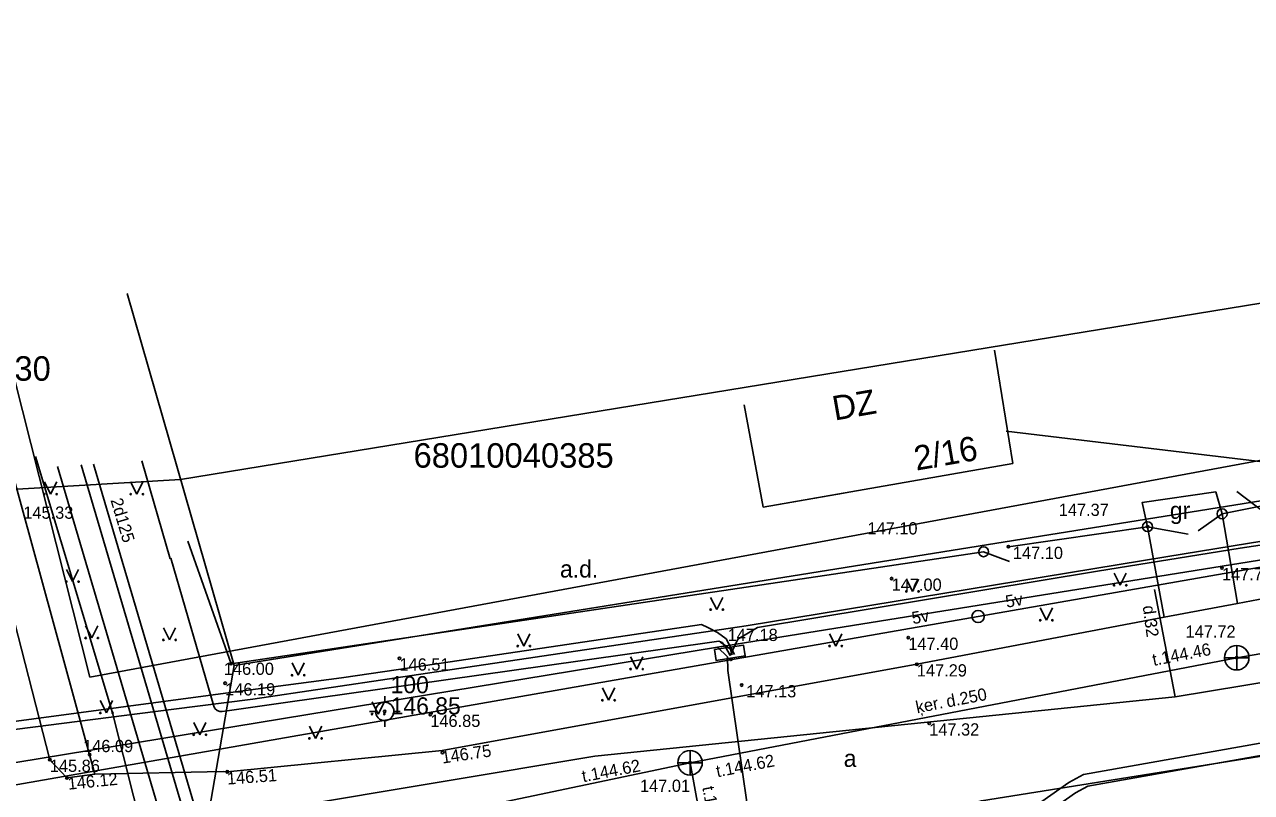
# Model space of a CAD drawing. Extents: x 728492 to 729038, y 272968 to 273171.
# Drawn here: x 728538.7 to 728588.9, y 273054.5 to 273085.8 of the extents above; entities that cross this region are included whole.
import ezdxf

# ---------------------------------------------------------------- set-up
doc = ezdxf.new("R2010")
doc.units = 0
for name, color, linetype in [('APGR_SARK_####_####_#', 7, 'Continuous'), ('BUVE_EKAS_####_####_#', 7, 'Continuous'), ('BUVE_EKAS_ADRS_TKST_#', 7, 'Continuous'), ('BUVE_EKAS_RAKS_TKST_#', 7, 'Continuous'), ('CELI_CAPM_####_####_#', 7, 'Continuous'), ('CELI_CMAL_####_####_#', 7, 'Continuous'), ('CELI_CSEG_####_TKST_#', 7, 'Continuous'), ('CELI_SEGL_####_####_#', 7, 'Continuous'), ('ELEK_ELEM_####_####_#', 7, 'Continuous'), ('ELEK_VADP_VSPR_####_#', 7, 'Continuous'), ('ELEK_VADP_ZSPR_####_#', 7, 'Continuous'), ('ELEK_VADV_ZSPR_####_#', 7, 'Continuous'), ('ELEK_VADV_ZSPR_TKST_#', 7, 'Continuous'), ('GEOD_ELEM_####_####_#', 7, 'Continuous'), ('GEOD_ELEM_####_TKST_#', 7, 'Continuous'), ('Level 7', 7, 'Continuous'), ('NORB_ELEM_####_####_#', 7, 'Continuous'), ('NORB_ZOGS_BARJ_####_#', 7, 'Continuous'), ('NORB_ZOGS_ZSTP_####_#', 7, 'Continuous'), ('RAMI_UZMR_####_####_#', 7, 'Continuous'), ('RELJ_AATZ_####_TKST_#', 7, 'Continuous'), ('RELJ_ELEM_####_####_#', 7, 'Continuous'), ('ROBZ_KADS_####_TKST_#', 7, 'Continuous'), ('ROBZ_UZMR_####_####_#', 7, 'Continuous'), ('SAKK_KKAN_####_####_#', 7, 'Continuous'), ('SAKT_VADP_KABE_####_#', 7, 'Continuous'), ('SAKT_VADV_KLIN_####_#', 7, 'Continuous'), ('SILT_VADP_UDEN_####_#', 7, 'Continuous'), ('SILT_VADP_UDEN_TKST_#', 7, 'Continuous'), ('SKAN_ELEM_####_####_#', 7, 'Continuous'), ('SKAN_VADP_PAST_####_#', 7, 'Continuous'), ('SKAN_VADP_PAST_TKST_#', 7, 'Continuous'), ('TERT_ELEM_####_####_#', 7, 'Continuous'), ('TERT_IZMT_####_TKST_#', 7, 'Continuous'), ('UDTK_VADP_UDEN_####_#', 7, 'Continuous'), ('UDTK_VADP_UDEN_TKST_#', 7, 'Continuous')]:
    doc.layers.add(name, color=color, linetype=linetype)

msp = doc.modelspace()

# ---------------------------------------------------------------- linework, layer by layer
at = {"layer": 'APGR_SARK_####_####_#'}
for points in [[(728659.143, 273080.982), (728541.407, 273059.185)], [(728541.407, 273059.185), (728536.919, 273076.93)]]:
    msp.add_lwpolyline(points, dxfattribs=at)
at = {"layer": 'BUVE_EKAS_####_####_#'}
for p, q in [((728578.38, 273072.545), (728579.123, 273067.904)), ((728568.928, 273066.121), (728568.149, 273070.31)), ((728579.123, 273067.904), (728568.928, 273066.121)), ((728572.204, 273066.694), (728568.928, 273066.121))]:
    msp.add_line(p, q, dxfattribs=at)
at = {"layer": 'CELI_CAPM_####_####_#'}
msp.add_line((728537.212, 273065.791), (728539.777, 273055.81), dxfattribs=at)
msp.add_lwpolyline([(728591.431, 273056.294), (728577.849, 273054.135), (728577.526, 273054.029), (728577.203, 273053.778), (728577.017, 273053.345), (728577.072, 273052.432)], dxfattribs=at)
at = {"layer": 'CELI_CMAL_####_####_#'}
for p, q in [((728541.62, 273055.225), (728538.209, 273067.671)), ((728588.309, 273062.194), (728590.22, 273062.556)), ((728575.205, 273059.709), (728585.316, 273061.626)), ((728555.804, 273056.19), (728575.205, 273059.709)), ((728547.029, 273055.314), (728555.804, 273056.19)), ((728541.62, 273055.225), (728546.857, 273055.329)), ((728546.857, 273055.329), (728547.029, 273055.314))]:
    msp.add_line(p, q, dxfattribs=at)
for points in [[(728584.631, 273065.328), (728584.407, 273066.315), (728587.419, 273066.752), (728587.68, 273065.855)], [(728587.68, 273065.855), (728588.309, 273062.194)], [(728584.631, 273065.328), (728585.316, 273061.626)], [(728541.62, 273055.225), (728541.62, 273055.225), (728540.474, 273055.066), (728539.777, 273055.81)]]:
    msp.add_lwpolyline(points, dxfattribs=at)
at = {"layer": 'CELI_SEGL_####_####_#'}
msp.add_line((728585.316, 273061.626), (728588.309, 273062.194), dxfattribs=at)
at = {"layer": 'ELEK_ELEM_####_####_#'}
msp.add_lwpolyline([(728566.936, 273060.306), (728568.121, 273060.494), (728568.191, 273060.05), (728567.006, 273059.861)], close=True, dxfattribs=at)
msp.add_circle((728577.706, 273061.659), 0.25, dxfattribs=at)
at = {"layer": 'ELEK_VADP_VSPR_####_#'}
for points in [[(728609.286, 273080.058), (728607.971, 273079.223), (728608.297, 273067.03), (728567.061, 273060.412)], [(728528.24, 273065.605), (728528.561, 273065.605), (728531.497, 273054.565), (728567.061, 273060.412)]]:
    msp.add_lwpolyline(points, dxfattribs=at)
at = {"layer": 'ELEK_VADP_ZSPR_####_#'}
for points in [[(728537.081, 273033.933), (728536.029, 273037.608), (728532.423, 273051.927), (728532.247, 273053.87), (728532.195, 273055.313), (728532.733, 273055.949), (728533.306, 273056.402), (728544.74, 273057.861), (728548.075, 273058.286), (728556.859, 273059.593), (728568.226, 273061.284), (728585.454, 273064.109), (728594.552, 273065.598), (728599.536, 273066.281), (728606.829, 273067.282), (728608.394, 273067.733), (728608.806, 273068.923), (728608.813, 273069.373), (728608.935, 273077.264)], [(728609.132, 273076.972), (728609.028, 273069.268), (728608.736, 273067.883), (728608.238, 273067.455), (728607.796, 273067.368), (728594.151, 273065.314), (728588.415, 273064.454), (728582.59, 273063.515), (728568.697, 273061.216), (728567.895, 273060.73), (728567.578, 273060.071)], [(728543.537, 273068.016), (728544.691, 273064.02)], [(728544.718, 273064.048), (728546.483, 273057.995), (728546.526, 273057.907), (728546.614, 273057.824), (728546.728, 273057.782), (728546.813, 273057.782), (728547.021, 273057.811), (728549.405, 273058.149), (728559.999, 273059.648), (728566.831, 273060.615), (728567.112, 273060.646), (728567.249, 273060.596), (728567.381, 273060.426), (728567.578, 273060.071)], [(728567.753, 273060.114), (728567.41, 273060.752), (728567.065, 273061.013), (728566.663, 273061.214), (728566.411, 273061.34), (728554.029, 273059.497), (728551.697, 273059.159), (728548.184, 273058.69), (728544.318, 273058.174), (728533.922, 273056.787), (728532.347, 273056.437), (728531.53, 273056.671), (728530.78, 273059.779)], [(728568.854, 273049.927), (728567.486, 273059.454), (728567.463, 273060.008)]]:
    msp.add_lwpolyline(points, dxfattribs=at)
at = {"layer": 'ELEK_VADV_ZSPR_####_#'}
for p, q in [((728577.706, 273061.659), (728617.923, 273068.708)), ((728530.877, 273053.467), (728577.706, 273061.659))]:
    msp.add_line(p, q, dxfattribs=at)
at = {"layer": 'GEOD_ELEM_####_####_#'}
for p, q in [((728553.461, 273058.158), (728553.461, 273058.408)), ((728552.836, 273057.783), (728553.086, 273057.783)), ((728553.461, 273057.158), (728553.461, 273057.408)), ((728553.836, 273057.783), (728554.086, 273057.783))]:
    msp.add_line(p, q, dxfattribs=at)
for radius in [0.375, 0.05]:
    msp.add_circle((728553.461, 273057.783), radius, dxfattribs=at)
at = {"layer": 'Level 7'}
msp.add_line((728567.061, 273060.412), (728567.463, 273060.008), dxfattribs=at)
msp.add_lwpolyline([(728567.182, 273060.614), (728567.584, 273060.331), (728567.665, 273060.089)], dxfattribs=at)
at = {"layer": 'NORB_ELEM_####_####_#'}
for centre in [(728587.68, 273065.855), (728584.631, 273065.328), (728577.931, 273064.305)]:
    msp.add_circle(centre, 0.202, dxfattribs=at)
at = {"layer": 'NORB_ZOGS_BARJ_####_#'}
for points in [[(728586.696, 273065.158), (728587.68, 273065.855)], [(728584.631, 273065.328), (728586.285, 273065.026)], [(728577.931, 273064.305), (728578.991, 273063.904)]]:
    msp.add_lwpolyline(points, dxfattribs=at)
at = {"layer": 'NORB_ZOGS_ZSTP_####_#'}
for points in [[(728587.68, 273065.855), (728594.005, 273067.114)], [(728578.944, 273064.509), (728584.631, 273065.328)], [(728545.412, 273064.735), (728547.181, 273059.731), (728577.931, 273064.305)]]:
    msp.add_lwpolyline(points, dxfattribs=at)
at = {"layer": 'RAMI_UZMR_####_####_#'}
for points in [[(728726.814, 273102.175), (728686.914, 273096.216), (728659.323, 273094.615), (728619.629, 273079.414), (728545.121, 273067.256)], [(728545.121, 273067.256), (728525.538, 273066.106), (728511.145, 273059.016), (728527.731, 273033.328), (728550.271, 273033.197), (728572.013, 273034.886), (728580.562, 273045.27), (728653.673, 273058.931), (728671.713, 273053.291), (728688.721, 273058.407), (728702.149, 273066.922)]]:
    msp.add_lwpolyline(points, dxfattribs=at)
at = {"layer": 'RELJ_ELEM_####_####_#'}
for centre in [(728584.631, 273065.328), (728578.944, 273064.509), (728587.672, 273063.64), (728574.174, 273063.211), (728574.855, 273060.797), (728554.064, 273059.951), (728567.609, 273059.906), (728588.276, 273059.976), (728547.181, 273059.731), (728575.205, 273059.709), (728546.942, 273058.935), (728568.047, 273058.857), (728553.461, 273057.783), (728555.323, 273057.647), (728575.71, 273057.297), (728539.777, 273055.81), (728541.407, 273056.021), (728555.821, 273056.102), (728547.029, 273055.314), (728565.936, 273055.685), (728540.474, 273055.066)]:
    msp.add_circle(centre, 0.05, dxfattribs=at)
at = {"layer": 'ROBZ_UZMR_####_####_#'}
for p, q in [((728547.311, 273059.662), (728542.932, 273074.849)), ((728597.584, 273067.721), (728547.311, 273059.662)), ((728547.311, 273059.662), (728544.976, 273046.06))]:
    msp.add_line(p, q, dxfattribs=at)
at = {"layer": 'SAKK_KKAN_####_####_#'}
msp.add_lwpolyline([(728540.095, 273067.793), (728546.092, 273047.448), (728546.377, 273046.751), (728547.961, 273042.009), (728549.129, 273037.471), (728550.271, 273033.197)], dxfattribs=at)
at = {"layer": 'SAKT_VADP_KABE_####_#'}
msp.add_lwpolyline([(728549.129, 273037.471), (728545.783, 273044.05), (728542.34, 273057.723), (728539.193, 273068.196)], dxfattribs=at)
at = {"layer": 'SAKT_VADV_KLIN_####_#'}
msp.add_line((728578.857, 273069.237), (728635.134, 273062.502), dxfattribs=at)
at = {"layer": 'SILT_VADP_UDEN_####_#'}
for p, q in [((728547.012, 273047.706), (728541.056, 273067.855)), ((728547.492, 273047.847), (728541.567, 273067.888))]:
    msp.add_line(p, q, dxfattribs=at)
for points in [[(728554.662, 273032.952), (728554.113, 273035.473), (728554.267, 273035.774), (728581.419, 273054.878), (728582.018, 273055.208), (728610.89, 273060.328), (728630.183, 273063.782), (728638.039, 273065.289), (728652.893, 273068.386), (728653.925, 273076.859), (728654.802, 273077.089)], [(728555.193, 273032.922), (728554.64, 273035.405), (728554.656, 273035.436), (728581.684, 273054.453), (728582.187, 273054.73), (728610.978, 273059.835), (728630.274, 273063.29), (728638.144, 273064.8), (728653.493, 273067.873), (728654.384, 273076.462), (728654.897, 273076.597)]]:
    msp.add_lwpolyline(points, dxfattribs=at)
at = {"layer": 'SKAN_ELEM_####_####_#'}
for p, q in [((728588.276, 273059.476), (728588.276, 273060.476)), ((728587.776, 273059.976), (728588.776, 273059.976)), ((728565.936, 273055.185), (728565.936, 273056.185)), ((728565.436, 273055.685), (728566.436, 273055.685))]:
    msp.add_line(p, q, dxfattribs=at)
for centre in [(728588.276, 273059.976), (728565.936, 273055.685)]:
    msp.add_circle(centre, 0.5, dxfattribs=at)
at = {"layer": 'SKAN_VADP_PAST_####_#'}
for points in [[(728565.936, 273055.685), (728588.276, 273059.976), (728595.572, 273061.244), (728588.275, 273066.761)], [(728536.573, 273049.518), (728565.936, 273055.685), (728568.908, 273039.465), (728569.266, 273036.186)]]:
    msp.add_lwpolyline(points, dxfattribs=at)
at = {"layer": 'TERT_ELEM_####_####_#'}
for p, q in [((728539.56, 273067.157), (728539.81, 273066.657)), ((728539.81, 273066.657), (728540.06, 273067.157)), ((728543.08, 273067.157), (728543.33, 273066.657)), ((728543.33, 273066.657), (728543.58, 273067.157)), ((728540.452, 273063.584), (728540.702, 273063.084)), ((728540.702, 273063.084), (728540.952, 273063.584)), ((728583.264, 273063.436), (728583.514, 273062.936)), ((728583.514, 273062.936), (728583.764, 273063.436)), ((728574.776, 273063.184), (728575.026, 273062.684)), ((728575.026, 273062.684), (728575.276, 273063.184)), ((728566.779, 273062.442), (728567.029, 273061.942)), ((728567.029, 273061.942), (728567.279, 273062.442)), ((728580.246, 273062.008), (728580.496, 273061.508)), ((728580.496, 273061.508), (728580.746, 273062.008)), ((728541.241, 273061.282), (728541.491, 273060.782)), ((728541.491, 273060.782), (728541.741, 273061.282)), ((728544.418, 273061.202), (728544.668, 273060.702)), ((728544.668, 273060.702), (728544.918, 273061.202)), ((728558.896, 273060.953), (728559.146, 273060.453)), ((728559.146, 273060.453), (728559.396, 273060.953)), ((728571.638, 273060.953), (728571.888, 273060.453)), ((728571.888, 273060.453), (728572.138, 273060.953)), ((728563.507, 273060.01), (728563.757, 273059.51)), ((728563.757, 273059.51), (728564.007, 273060.01)), ((728549.674, 273059.762), (728549.924, 273059.262)), ((728549.924, 273059.262), (728550.174, 273059.762)), ((728562.358, 273058.74), (728562.608, 273058.24)), ((728562.608, 273058.24), (728562.858, 273058.74)), ((728541.84, 273058.224), (728542.09, 273057.724)), ((728542.09, 273057.724), (728542.34, 273058.224)), ((728552.946, 273058.174), (728553.196, 273057.674)), ((728553.196, 273057.674), (728553.446, 273058.174)), ((728545.658, 273057.33), (728545.908, 273056.83)), ((728545.908, 273056.83), (728546.158, 273057.33)), ((728550.385, 273057.179), (728550.635, 273056.679)), ((728550.635, 273056.679), (728550.885, 273057.179))]:
    msp.add_line(p, q, dxfattribs=at)
for centre, radius in [((728539.559, 273066.657), 0.028), ((728540.059, 273066.657), 0.0263), ((728543.08, 273066.657), 0.028), ((728543.58, 273066.657), 0.0263), ((728540.452, 273063.083), 0.028), ((728540.952, 273063.083), 0.0263), ((728583.263, 273062.936), 0.028), ((728583.763, 273062.936), 0.0263), ((728574.776, 273062.684), 0.028), ((728575.276, 273062.684), 0.0263), ((728566.779, 273061.942), 0.028), ((728567.279, 273061.942), 0.0263), ((728580.245, 273061.508), 0.028), ((728580.745, 273061.508), 0.0263), ((728541.241, 273060.782), 0.028), ((728541.741, 273060.782), 0.0263), ((728544.418, 273060.701), 0.028), ((728544.918, 273060.701), 0.0263), ((728558.896, 273060.453), 0.028), ((728559.396, 273060.453), 0.0263), ((728571.638, 273060.453), 0.028), ((728572.138, 273060.453), 0.0263), ((728563.507, 273059.51), 0.028), ((728564.007, 273059.51), 0.0263), ((728549.674, 273059.262), 0.028), ((728550.174, 273059.262), 0.0263), ((728562.358, 273058.24), 0.028), ((728562.858, 273058.24), 0.0263), ((728541.84, 273057.723), 0.028), ((728542.34, 273057.723), 0.0263), ((728552.946, 273057.674), 0.028), ((728553.446, 273057.674), 0.0263), ((728545.658, 273056.83), 0.028), ((728546.158, 273056.83), 0.0263), ((728550.385, 273056.678), 0.028), ((728550.885, 273056.678), 0.0263)]:
    msp.add_circle(centre, radius, dxfattribs=at)
at = {"layer": 'UDTK_VADP_UDEN_####_#'}
for points in [[(728536.753, 273051.73), (728562.041, 273055.954), (728585.763, 273058.374), (728605.397, 273061.619), (728606.945, 273061.767), (728607.469, 273061.897), (728613.688, 273063.022), (728614.11, 273063.005), (728657.437, 273069.243)], [(728584.922, 273062.757), (728585.763, 273058.374)]]:
    msp.add_lwpolyline(points, dxfattribs=at)

# ---------------------------------------------------------------- texts
at = {"layer": 'BUVE_EKAS_ADRS_TKST_#'}
msp.add_text('2/16', height=1, rotation=9.918, dxfattribs=at).set_placement((728575.182, 273067.617))
at = {"layer": 'BUVE_EKAS_RAKS_TKST_#'}
msp.add_text('DZ', height=1, rotation=9.9183, dxfattribs=at).set_placement((728571.848, 273069.66))
at = {"layer": 'CELI_CSEG_####_TKST_#'}
for s, p in [('gr', (728585.543, 273065.644)), ('a', (728572.217, 273055.515))]:
    msp.add_text(s, height=0.7, dxfattribs=at).set_placement(p)
at = {"layer": 'ELEK_VADV_ZSPR_TKST_#'}
for rotation, p in [(9.9415, (728578.873, 273062.016)), (9.9225, (728575.043, 273061.345))]:
    msp.add_text('5v', height=0.5, rotation=rotation, dxfattribs=at).set_placement(p)
at = {"layer": 'GEOD_ELEM_####_TKST_#'}
for s, p in [('100', (728553.702, 273058.524)), ('146.85', (728553.704, 273057.659))]:
    msp.add_text(s, height=0.7, dxfattribs=at).set_placement(p)
at = {"layer": 'RELJ_AATZ_####_TKST_#'}
for s, p in [('145.33', (728538.693, 273065.653)), (' 147.37', (728580.817, 273065.769)), (' 147.10', (728573.001, 273065.011)), (' 147.10', (728578.944, 273064.009)), ('147.76', (728587.672, 273063.14)), ('147.00', (728574.174, 273062.711)), (' 147.18', (728567.289, 273060.659)), ('147.40', (728574.855, 273060.297)), ('146.51', (728554.064, 273059.451)), (' 146.00', (728546.702, 273059.275)), ('147.29', (728575.205, 273059.209)), ('146.19', (728546.942, 273058.435)), (' 147.13', (728568.047, 273058.357)), ('146.85', (728555.323, 273057.147)), ('147.32', (728575.71, 273056.797)), (' 146.09', (728540.951, 273056.12)), ('145.86', (728539.777, 273055.31))]:
    msp.add_text(s, height=0.5, dxfattribs=at).set_placement(p)
for s, rotation, p in [('146.75', 8.3901, (728555.822, 273055.65)), ('146.51', 4.1381, (728547.033, 273054.791)), (' 146.12', 5.6921, (728540.349, 273054.564))]:
    msp.add_text(s, height=0.5, rotation=rotation, dxfattribs=at).set_placement(p)
at = {"layer": 'ROBZ_KADS_####_TKST_#'}
for s, p in [('68010040730', (728531.636, 273071.292)), ('68010040385', (728554.638, 273067.74))]:
    msp.add_text(s, height=1, dxfattribs=at).set_placement(p)
at = {"layer": 'SILT_VADP_UDEN_TKST_#'}
msp.add_text('2d125', height=0.5, rotation=286.469, dxfattribs=at).set_placement((728542.252, 273066.417))
at = {"layer": 'SKAN_ELEM_####_####_#'}
for s, p in [('147.72', (728586.184, 273060.793)), ('147.01', (728563.892, 273054.496))]:
    msp.add_text(s, height=0.5, dxfattribs=at).set_placement(p)
at = {"layer": 'SKAN_VADP_PAST_TKST_#'}
for s, rotation, p in [('t.144.46', 10.873, (728584.88, 273059.64)), ('d.250', 10.873, (728576.457, 273057.942)), ('ķer.', 11.861, (728575.217, 273057.697)), ('t.144.62', 10.873, (728561.569, 273054.887)), ('t.144.62', 10.873, (728567.052, 273055.09)), ('t.144.82', 280.383, (728566.435, 273054.681))]:
    msp.add_text(s, height=0.5, rotation=rotation, dxfattribs=at).set_placement(p)
at = {"layer": 'TERT_IZMT_####_TKST_#'}
msp.add_text('a.d.', height=0.7, dxfattribs=at).set_placement((728560.623, 273063.253))
at = {"layer": 'UDTK_VADP_UDEN_TKST_#'}
msp.add_text('d.32', height=0.5, rotation=277.4522, dxfattribs=at).set_placement((728584.432, 273062.081))

doc.saveas('drawing.dxf')
